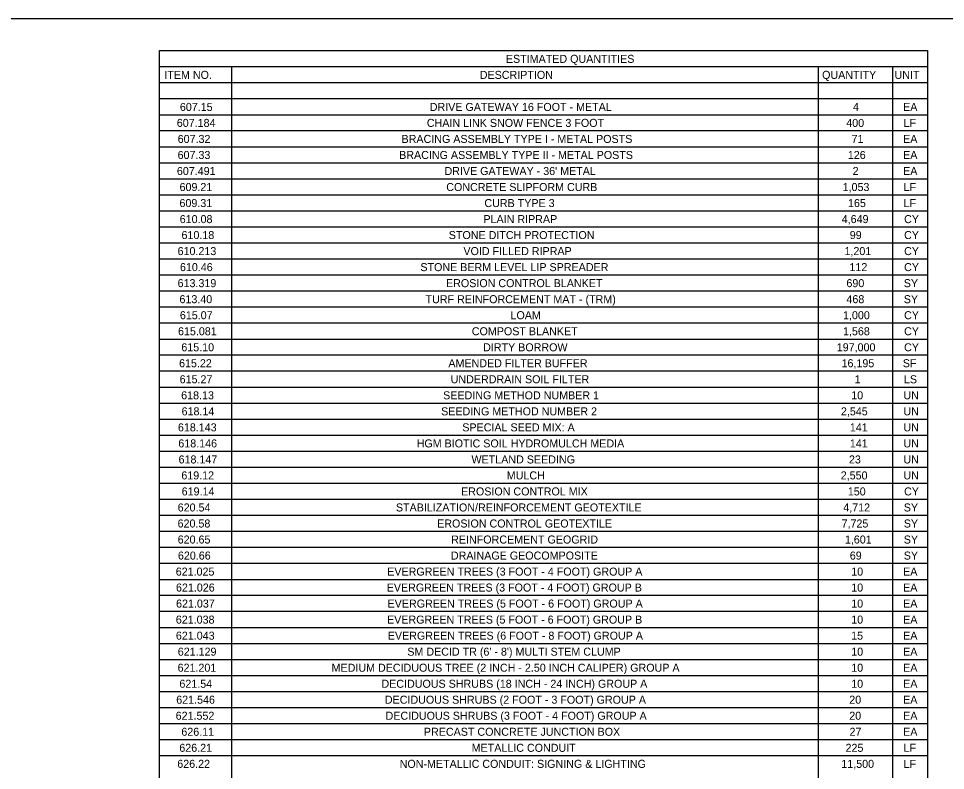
# Model space of a CAD drawing. Extents: x -18.7 to 5.6, y -2.7 to 4.
# Drawn here: x -15.505 to -14.366, y 3.09 to 4.014 of the extents above; entities that cross this region are included whole.
import ezdxf

# ---------------------------------------------------------------- set-up
doc = ezdxf.new("R2010")
doc.units = 0
doc.layers.add('ANNOTATION', color=7, linetype='Continuous')
doc.layers.add('BORDER', color=7, linetype='Continuous')

msp = doc.modelspace()

# ---------------------------------------------------------------- linework, layer by layer
at = {"layer": 'ANNOTATION'}
msp.add_lwpolyline([(-17.663, 4.0141), (-13.3075, 4.0141), (-13.3075, 2.1719), (-17.663, 2.1719)], close=True, dxfattribs=at)
at = {"layer": 'BORDER'}
for p, q in [((-15.3321, 3.9551), (-14.3878, 3.9551)), ((-15.2435, 3.9551), (-15.2435, 2.2424)), ((-14.5222, 3.9551), (-14.5222, 2.2424)), ((-14.4308, 3.9551), (-14.4308, 2.2424)), ((-15.3321, 3.9354), (-14.3878, 3.9354)), ((-15.3321, 3.9157), (-14.3878, 3.9157)), ((-15.3321, 3.896), (-14.3878, 3.896)), ((-15.3321, 3.8764), (-14.3878, 3.8764)), ((-15.3321, 3.8567), (-14.3878, 3.8567)), ((-15.3321, 3.837), (-14.3878, 3.837)), ((-15.3321, 3.8173), (-14.3878, 3.8173)), ((-15.3321, 3.7976), (-14.3878, 3.7976)), ((-15.3321, 3.7779), (-14.3878, 3.7779)), ((-15.3321, 3.7582), (-14.3878, 3.7582)), ((-15.3321, 3.7386), (-14.3878, 3.7386)), ((-15.3321, 3.7189), (-14.3878, 3.7189)), ((-15.3321, 3.6992), (-14.3878, 3.6992)), ((-15.3321, 3.6795), (-14.3878, 3.6795)), ((-15.3321, 3.6598), (-14.3878, 3.6598)), ((-15.3321, 3.6401), (-14.3878, 3.6401)), ((-15.3321, 3.6204), (-14.3878, 3.6204)), ((-15.3321, 3.6008), (-14.3878, 3.6008)), ((-15.3321, 3.5811), (-14.3878, 3.5811)), ((-15.3321, 3.5614), (-14.3878, 3.5614)), ((-15.3321, 3.5417), (-14.3878, 3.5417)), ((-15.3321, 3.522), (-14.3878, 3.522)), ((-15.3321, 3.5023), (-14.3878, 3.5023)), ((-15.3321, 3.4826), (-14.3878, 3.4826)), ((-15.3321, 3.463), (-14.3878, 3.463)), ((-15.3321, 3.4433), (-14.3878, 3.4433)), ((-15.3321, 3.4236), (-14.3878, 3.4236)), ((-15.3321, 3.4039), (-14.3878, 3.4039)), ((-15.3321, 3.3842), (-14.3878, 3.3842)), ((-15.3321, 3.3645), (-14.3878, 3.3645)), ((-15.3321, 3.3448), (-14.3878, 3.3448)), ((-15.3321, 3.3251), (-14.3878, 3.3251)), ((-15.3321, 3.3055), (-14.3878, 3.3055)), ((-15.3321, 3.2858), (-14.3878, 3.2858)), ((-15.3321, 3.2661), (-14.3878, 3.2661)), ((-15.3321, 3.2464), (-14.3878, 3.2464)), ((-15.3321, 3.2267), (-14.3878, 3.2267)), ((-15.3321, 3.207), (-14.3878, 3.207)), ((-15.3321, 3.1873), (-14.3878, 3.1873)), ((-15.3321, 3.1677), (-14.3878, 3.1677)), ((-15.3321, 3.148), (-14.3878, 3.148)), ((-15.3321, 3.1283), (-14.3878, 3.1283)), ((-15.3321, 3.1086), (-14.3878, 3.1086))]:
    msp.add_line(p, q, dxfattribs=at)
msp.add_lwpolyline([(-15.3321, 3.9748), (-14.3878, 3.9748), (-14.3878, 2.2424), (-15.3321, 2.2424)], close=True, dxfattribs=at)

# ---------------------------------------------------------------- texts
at = {"layer": 'ANNOTATION'}
for s, height, p in [('607.15', 0.00984, (-15.3071, 3.9006)), ('DRIVE GATEWAY 16 FOOT - METAL', 0.009843, (-14.9999, 3.9006)), ('4', 0.00984, (-14.4796, 3.9006)), ('EA', 0.00984, (-14.4179, 3.9006)), ('607.184', 0.00984, (-15.3109, 3.881)), ('CHAIN LINK SNOW FENCE 3 FOOT', 0.009843, (-15.0035, 3.881)), ('400', 0.00984, (-14.4878, 3.881)), ('LF', 0.00984, (-14.4173, 3.881)), ('607.32', 0.00984, (-15.3098, 3.8613)), ('BRACING ASSEMBLY TYPE I - METAL POSTS', 0.009843, (-15.0346, 3.8613)), ('71', 0.00984, (-14.4813, 3.8613)), ('EA', 0.00984, (-14.4179, 3.8613)), ('607.33', 0.00984, (-15.3099, 3.8416)), ('BRACING ASSEMBLY TYPE II - METAL POSTS', 0.009843, (-15.0375, 3.8416)), ('126', 0.00984, (-14.4859, 3.8416)), ('EA', 0.00984, (-14.4179, 3.8416)), ('607.491', 0.00984, (-15.3108, 3.8219)), ("DRIVE GATEWAY - 36' METAL", 0.009843, (-14.9818, 3.8219)), ('2', 0.00984, (-14.48, 3.8219)), ('EA', 0.00984, (-14.4179, 3.8219)), ('609.21', 0.00984, (-15.3075, 3.8022)), ('CONCRETE SLIPFORM CURB', 0.009843, (-14.9796, 3.8022)), ('1,053', 0.00984, (-14.4923, 3.8022)), ('LF', 0.00984, (-14.4173, 3.8022)), ('609.31', 0.00984, (-15.3076, 3.7825)), ('CURB TYPE 3', 0.009843, (-14.9327, 3.7825)), ('165', 0.00984, (-14.4857, 3.7825)), ('LF', 0.00984, (-14.4173, 3.7825)), ('610.08', 0.00984, (-15.3073, 3.7628)), ('PLAIN RIPRAP', 0.009843, (-14.9339, 3.7628)), ('4,649', 0.00984, (-14.4934, 3.7628)), ('CY', 0.00984, (-14.4167, 3.7628)), ('610.18', 0.00984, (-15.3051, 3.7432)), ('STONE DITCH PROTECTION', 0.009843, (-14.9765, 3.7432)), ('99', 0.00984, (-14.4835, 3.7432)), ('CY', 0.00984, (-14.4167, 3.7432)), ('610.213', 0.00984, (-15.3099, 3.7235)), ('VOID FILLED RIPRAP', 0.009843, (-14.9585, 3.7235)), ('1,201', 0.00984, (-14.49, 3.7235)), ('CY', 0.00984, (-14.4167, 3.7235)), ('610.46', 0.00984, (-15.307, 3.7038)), ('STONE BERM LEVEL LIP SPREADER', 0.009843, (-15.0114, 3.7038)), ('112', 0.00984, (-14.4839, 3.7038)), ('CY', 0.00984, (-14.4167, 3.7038)), ('613.319', 0.00984, (-15.3099, 3.6841)), ('EROSION CONTROL BLANKET', 0.009843, (-14.9799, 3.6841)), ('690', 0.00984, (-14.4876, 3.6841)), ('SY', 0.00984, (-14.4171, 3.6841)), ('613.40', 0.00984, (-15.3076, 3.6644)), ('TURF REINFORCEMENT MAT - (TRM)', 0.009843, (-15.0051, 3.6644)), ('468', 0.00984, (-14.4876, 3.6644)), ('SY', 0.00984, (-14.4171, 3.6644)), ('615.07', 0.00984, (-15.3071, 3.6447)), ('LOAM', 0.00984, (-14.9006, 3.6447)), ('1,000', 0.00984, (-14.4918, 3.6447)), ('CY', 0.00984, (-14.4167, 3.6447)), ('615.081', 0.00984, (-15.3094, 3.625)), ('COMPOST BLANKET', 0.009843, (-14.9482, 3.625)), ('1,568', 0.00984, (-14.4918, 3.625)), ('CY', 0.00984, (-14.4167, 3.625)), ('615.10', 0.00984, (-15.3053, 3.6053)), ('DIRTY BORROW', 0.009843, (-14.9343, 3.6053)), ('197,000', 0.00984, (-14.4995, 3.6053)), ('CY', 0.00984, (-14.4167, 3.6053)), ('615.22', 0.00984, (-15.3081, 3.5857)), ('AMENDED FILTER BUFFER ', 0.009843, (-14.977, 3.5857)), ('16,195', 0.00984, (-14.4936, 3.5857)), ('SF', 0.00984, (-14.4183, 3.5857)), ('615.27', 0.00984, (-15.3074, 3.566)), ('UNDERDRAIN SOIL FILTER', 0.009843, (-14.9742, 3.566)), ('1', 0.00984, (-14.4776, 3.566)), ('LS', 0.00984, (-14.4169, 3.566)), ('618.13', 0.00984, (-15.3055, 3.5463)), ('SEEDING METHOD NUMBER 1', 0.009843, (-14.9834, 3.5463)), ('10', 0.00984, (-14.4817, 3.5463)), ('UN', 0.00984, (-14.4176, 3.5463)), ('618.14', 0.00984, (-15.305, 3.5266)), ('SEEDING METHOD NUMBER 2', 0.009843, (-14.9859, 3.5266)), ('2,545', 0.00984, (-14.4944, 3.5266)), ('UN', 0.00984, (-14.4176, 3.5266)), ('618.143', 0.00984, (-15.3095, 3.5069)), ('SPECIAL SEED MIX: A', 0.009843, (-14.9599, 3.5069)), ('141', 0.00984, (-14.4834, 3.5069)), ('UN', 0.00984, (-14.4176, 3.5069)), ('618.146', 0.00984, (-15.309, 3.4872)), ('HGM BIOTIC SOIL HYDROMULCH MEDIA', 0.009843, (-15.016, 3.4872)), ('141', 0.00984, (-14.4834, 3.4872)), ('UN', 0.00984, (-14.4176, 3.4872)), ('618.147', 0.00984, (-15.3087, 3.4675)), ('WETLAND SEEDING', 0.009843, (-14.9486, 3.4675)), ('23', 0.00984, (-14.4845, 3.4675)), ('UN', 0.00984, (-14.4176, 3.4675)), ('619.12', 0.00984, (-15.3053, 3.4479)), ('MULCH', 0.00984, (-14.9052, 3.4479)), ('2,550', 0.00984, (-14.4946, 3.4479)), ('UN', 0.00984, (-14.4176, 3.4479)), ('619.14', 0.00984, (-15.3049, 3.4282)), ('EROSION CONTROL MIX', 0.009843, (-14.9614, 3.4282)), ('150', 0.00984, (-14.4859, 3.4282)), ('CY', 0.00984, (-14.4167, 3.4282)), ('STABILIZATION/REINFORCEMENT GEOTEXTILE', 0.009843, (-15.0415, 3.4085)), ('620.54', 0.00984, (-15.3098, 3.4085)), ('4,712', 0.00984, (-14.4915, 3.4085)), ('SY', 0.00984, (-14.4171, 3.4085)), ('620.58', 0.00984, (-15.3099, 3.3888)), ('EROSION CONTROL GEOTEXTILE', 0.009843, (-14.9908, 3.3888)), ('7,725', 0.00984, (-14.4936, 3.3888)), ('SY', 0.00984, (-14.4171, 3.3888)), ('620.65', 0.00984, (-15.3098, 3.3691)), ('REINFORCEMENT GEOGRID', 0.009843, (-14.9736, 3.3691)), ('1,601', 0.00984, (-14.4895, 3.3691)), ('SY', 0.00984, (-14.4171, 3.3691)), ('620.66', 0.00984, (-15.3095, 3.3494)), ('DRAINAGE GEOCOMPOSITE', 0.009843, (-14.9739, 3.3494)), ('69', 0.00984, (-14.4835, 3.3494)), ('SY', 0.00984, (-14.4171, 3.3494)), ('621.025', 0.00984, (-15.3122, 3.3297)), ('EVERGREEN TREES (3 FOOT - 4 FOOT) GROUP A', 0.009843, (-15.0522, 3.3297)), ('10', 0.00984, (-14.4817, 3.3297)), ('EA', 0.00984, (-14.4179, 3.3297)), ('621.026', 0.00984, (-15.3119, 3.3101)), ('EVERGREEN TREES (3 FOOT - 4 FOOT) GROUP B', 0.009843, (-15.0528, 3.3101)), ('10', 0.00984, (-14.4817, 3.3101)), ('EA', 0.00984, (-14.4179, 3.3101)), ('621.037', 0.00984, (-15.3118, 3.2904)), ('EVERGREEN TREES (5 FOOT - 6 FOOT) GROUP A', 0.009843, (-15.0518, 3.2904)), ('10', 0.00984, (-14.4817, 3.2904)), ('EA', 0.00984, (-14.4179, 3.2904)), ('621.038', 0.00984, (-15.3121, 3.2707)), ('EVERGREEN TREES (5 FOOT - 6 FOOT) GROUP B', 0.009843, (-15.0524, 3.2707)), ('10', 0.00984, (-14.4817, 3.2707)), ('EA', 0.00984, (-14.4179, 3.2707)), ('621.043', 0.00984, (-15.312, 3.251)), ('EVERGREEN TREES (6 FOOT - 8 FOOT) GROUP A', 0.009843, (-15.0515, 3.251)), ('15', 0.00984, (-14.4818, 3.251)), ('EA', 0.00984, (-14.4179, 3.251)), ('621.129', 0.00984, (-15.3097, 3.2313)), ("SM DECID TR (6' - 8') MULTI STEM CLUMP", 0.009843, (-15.0275, 3.2313)), ('10', 0.00984, (-14.4817, 3.2313)), ('EA', 0.00984, (-14.4179, 3.2313)), ('621.201', 0.00984, (-15.3099, 3.2116)), ('MEDIUM DECIDUOUS TREE (2 INCH - 2.50 INCH CALIPER) GROUP A', 0.009843, (-15.1206, 3.2116)), ('10', 0.00984, (-14.4817, 3.2116)), ('EA', 0.00984, (-14.4179, 3.2116)), ('621.54', 0.00984, (-15.3077, 3.1919)), ('DECIDUOUS SHRUBS (18 INCH - 24 INCH) GROUP A', 0.009843, (-15.0593, 3.1919)), ('10', 0.00984, (-14.4817, 3.1919)), ('EA', 0.00984, (-14.4179, 3.1919)), ('621.546', 0.00984, (-15.3116, 3.1723)), ('DECIDUOUS SHRUBS (2 FOOT - 3 FOOT) GROUP A', 0.009843, (-15.0551, 3.1723)), ('20', 0.00984, (-14.4841, 3.1723)), ('EA', 0.00984, (-14.4179, 3.1723)), ('621.552', 0.00984, (-15.3123, 3.1526)), ('DECIDUOUS SHRUBS (3 FOOT - 4 FOOT) GROUP A', 0.009843, (-15.0542, 3.1526)), ('20', 0.00984, (-14.4841, 3.1526)), ('EA', 0.00984, (-14.4179, 3.1526)), ('626.11', 0.00984, (-15.3053, 3.1329)), ('PRECAST CONCRETE JUNCTION BOX', 0.009843, (-15.0071, 3.1329)), ('27', 0.00984, (-14.4838, 3.1329)), ('EA', 0.00984, (-14.4179, 3.1329)), ('626.21', 0.00984, (-15.3078, 3.1132)), ('METALLIC CONDUIT', 0.009843, (-14.9484, 3.1132)), ('225', 0.00984, (-14.4887, 3.1132)), ('LF', 0.00984, (-14.4173, 3.1132)), ('626.22', 0.00984, (-15.3103, 3.0935)), ('NON-METALLIC CONDUIT: SIGNING & LIGHTING', 0.009843, (-15.0369, 3.0935)), ('11,500', 0.00984, (-14.4939, 3.0935)), ('LF', 0.00984, (-14.4173, 3.0935))]:
    msp.add_text(s, height=height, dxfattribs=at).set_placement(p)
at = {"layer": 'BORDER'}
for s, height, p in [('ESTIMATED QUANTITIES', 0.009843, (-14.9063, 3.9597)), ('ITEM NO.', 0.00984, (-15.3262, 3.94)), ('DESCRIPTION', 0.009843, (-14.9384, 3.94)), ('QUANTITY', 0.00984, (-14.5175, 3.94)), ('UNIT', 0.00984, (-14.4285, 3.94))]:
    msp.add_text(s, height=height, dxfattribs=at).set_placement(p)

doc.saveas('drawing.dxf')
